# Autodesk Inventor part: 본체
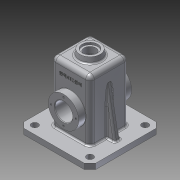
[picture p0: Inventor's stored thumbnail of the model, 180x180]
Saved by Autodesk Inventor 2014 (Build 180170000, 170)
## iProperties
Created: 2016-02
Part Number: 본체
Material: 알루미늄 6061
Document SubType Name: Modeling
Designer: 703-05
Density: 2.71 g/cm^3
Appearance: 알루미늄 - 평지
Mass: 935.961 g
Surface Area: 1045.55 cm^2
Volume: 345.373 cm^3
Author: 703-05
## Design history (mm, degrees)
sketch "스케치1"
  geometry: L1 (-65, 65)-(65, 65); L2 (65, 65)-(65, -65); L3 (65, -65)-(-65, -65); L4 (-65, -65)-(-65, 65); L5 (-65, 65)-(65, -65); L6 (65, 65)-(-65, -65); 1 further point
  constraints: 12 end point, 2 midpoint, 2 parallel, 1 horizontal, 1 perpendicular
  dimensions: "d0" = 130 distance of L2.end L3.end; "d1" = 130 distance of L1.end L2.end
extrude "돌출1" new body sketch "스케치1" distance "d2" = 10; taper "d3" = 0 deg
sketch "스케치2"
  geometry: L1 (-35, 35)-(35, 35); L2 (35, 35)-(35, -35); L3 (35, -35)-(-35, -35); L4 (-35, -35)-(-35, 35); L5 (-35, 35)-(35, -35); L6 (35, 35)-(-35, -35); 1 further point
  constraints: 12 end point, 2 midpoint, 2 parallel, 1 horizontal, 1 perpendicular
  dimensions: "d4" = 70 distance of L2.end L3.end; "d5" = 70 distance of L1.end L2.end
extrude "돌출2" join sketch "스케치2" distance "d6" = 110; taper "d7" = 0 deg
fillet "모깎기1" dims "d8" = 8
fillet "모깎기2" dims "d9" = 8
chamfer "모따기1" distance "d10" = 10; stored, may be unused: second distance "d11" = 2, angle "d12" = 45 deg
sketch "스케치3"
  geometry: L1 (-65, 55)-(-65, -55) reference; L2 (-55, -65)-(55, -65) reference; L3 (65, -55)-(65, 55) reference; L4 (55, 65)-(-55, 65) reference; 5 further points
  constraints: 2 horizontal alignment, 2 vertical alignment
  dimensions: "d13" = 15 distance from line of L4 point (-50, 50); "d14" = 15 distance from line of L1 point (-50, 50); "d15" = 15 distance from line of L2 point (-50, -50); "d16" = 15 distance from line of L3 point (50, -50)
hole "구멍1" sketch "스케치3" at (-50, 50), (50, 50), (50, -50), (-50, -50) diameter "d17" = 12; stored, may be unused: countersink angle "d21" = 90 deg, drill point angle "d23" = 118 deg; dims "d18" = 6, "d19" = 4, "d20" = 2, "d22" = 8
sketch "스케치4"
  geometry: L1 (-55, 10)-(55, 10) reference; L2 (35, 10)-(35, 112) reference; L3 (-35, 112)-(-35, 10) reference; L4 (50, 10)-(35, 95.069); L5 (-65, 10)-(-65, 0) reference; L6 (65, 0)-(65, 10) reference; 1 further point
  constraints: 2 end point, 2 point on line
  dimensions: "d24" = 100 deg angle of L1 L4; "d27" = 15 distance from line of L6 L4.start
feature "리브1" sketch "스케치4" dims "d28" = 1, "d29" = 10, "d30" = 0, "d31" = 0, "d32" = 1, "d33" = 1
fillet "모깎기3" dims "d34" = 3
fillet "모깎기4" dims "d35" = 3
sketch "스케치5"
  geometry: L1 (-55, 0)-(55, 0) reference; L2 (-27, 120)-(27, 120) reference; L3 (-30, 0)-(-30, 115); L4 (-30, 115)-(30, 115); L5 (30, 115)-(30, 0); L6 (-35, 13)-(-35, 112) reference; L7 (35, 112)-(35, 13) reference; 1 further point
  constraints: 6 end point, 3 perpendicular, 2 point on line
  dimensions: "d36" = 5 distance between parallel lines of L6 L3; "d37" = 5 distance between parallel lines of L7 L5; "d38" = 5 distance between parallel lines of L4 L2
extrude "돌출3" cut sketch "스케치5" stored distance "d39" = 60; taper "d40" = 0 deg
fillet "모깎기5" dims "d41" = 3
fillet "모깎기6" dims "d42" = 3
sketch "스케치6"
  geometry: C1 r 20 at (0, 0); 1 further point
  constraints: 1 centre point, 1 coincident
  dimensions: "d43" = 40 diameter of C1
extrude "돌출4" join sketch "스케치6" distance "d44" = 10; taper "d45" = -10 deg
fillet "모깎기7" dims "d46" = 3
hole "구멍2" diameter "d49" = 21; stored, may be unused: countersink angle "d53" = 90 deg, drill point angle "d55" = 118 deg; dims "d47" = 10, "d48" = 10, "d50" = 6, "d51" = 28, "d52" = 4, "d54" = 8
sketch "스케치7"
  geometry: L1 (82, -112)-(-28, -112) reference; C1 r 27.5 at (27, -57); 2 further points
  constraints: 1 centre point, 1 midpoint, 1 vertical alignment
  dimensions: "d56" = 55 diameter of C1; "d57" = 55 distance from line of L1 C1.centre
extrude "돌출5" join sketch "스케치7" distance "d58" = 13; taper "d59" = 0 deg
sketch "스케치8"
  geometry: L1 (-48, 82.5)-(-48, 27.5) reference; L2 (48, 82.5)-(48, 27.5) reference; L3 (48, 55)-(-48, 55); L4 (-23, 55)-(-23, 75.5); L5 (-30, 112)-(-30, 0) reference; L6 (30, 0)-(30, 112) reference; L7 (-23, 75.5)-(-30, 82.5); L8 (23, 55)-(23, 75.5); L9 (23, 75.5)-(30, 82.5); L10 (-30, 82.5)-(-30, 55); L11 (30, 82.5)-(30, 55); 1 further point
  constraints: 14 end point, 8 point on line, 2 equal length, 2 midpoint, 1 parallel, 1 perpendicular
  dimensions: "d60" = 7 distance between parallel lines of L5 L4; "d61" = 7 distance between parallel lines of L6 L8; "d62" = 135 deg angle of L5 L7; "d64" = 55 diameter of L7.end L3
revolve "회전1" sketch "스케치8" stored, may be unused: angle "d65" = 90 deg
hole "구멍3" diameter "d68" = 32; stored, may be unused: countersink angle "d72" = 90 deg, drill point angle "d74" = 118 deg; dims "d66" = 10, "d67" = 10, "d69" = 6, "d70" = 28, "d71" = 4, "d73" = 8
chamfer "모따기2" distance "d75" = 1; stored, may be unused: second distance "d76" = 2, angle "d77" = 45 deg
sketch "스케치9" dims "d78" = 45
  geometry: L1 (0, 0)-(0, 22.5); C1 r 17 at (0, 0) reference; 2 further points
  constraints: 2 coincident, 2 end point, 1 vertical, 1 vertical alignment, 2 other
hole "구멍4" sketch "스케치9" at (0, 22.5) diameter "d79" = 3.242; stored, may be unused: countersink angle "d83" = 90 deg, drill point angle "d85" = 118 deg; dims "d80" = 8, "d81" = 28, "d82" = 4, "d84" = 10
fillet "모깎기8" dims "d86" = 0.5
node "작업 평면1"
sketch "스케치10"
  geometry: L1 (35, 13)-(35, 112) reference; L2 (-18.237, 130)-(18.237, 130) reference; 2 further points
  constraints: 1 other
  dimensions: "d92" = 35 distance from line of L1 point (0, 100); "d93" = 30 distance from line of L2 point (0, 100)
feature "엠보싱1" sketch "스케치10" dims "d0" = 130, "d1" = 130, "d94" = 0.5, "d95" = 0
fillet "모깎기9" dims "d96" = 0.5
node "솔리드1"
mirror "대칭1"
mirror "대칭2"
pattern_circular "원형 패턴1" dims angle "d88" = 360 deg
mirror "대칭3"
other parameters: "d90" = -40.25
